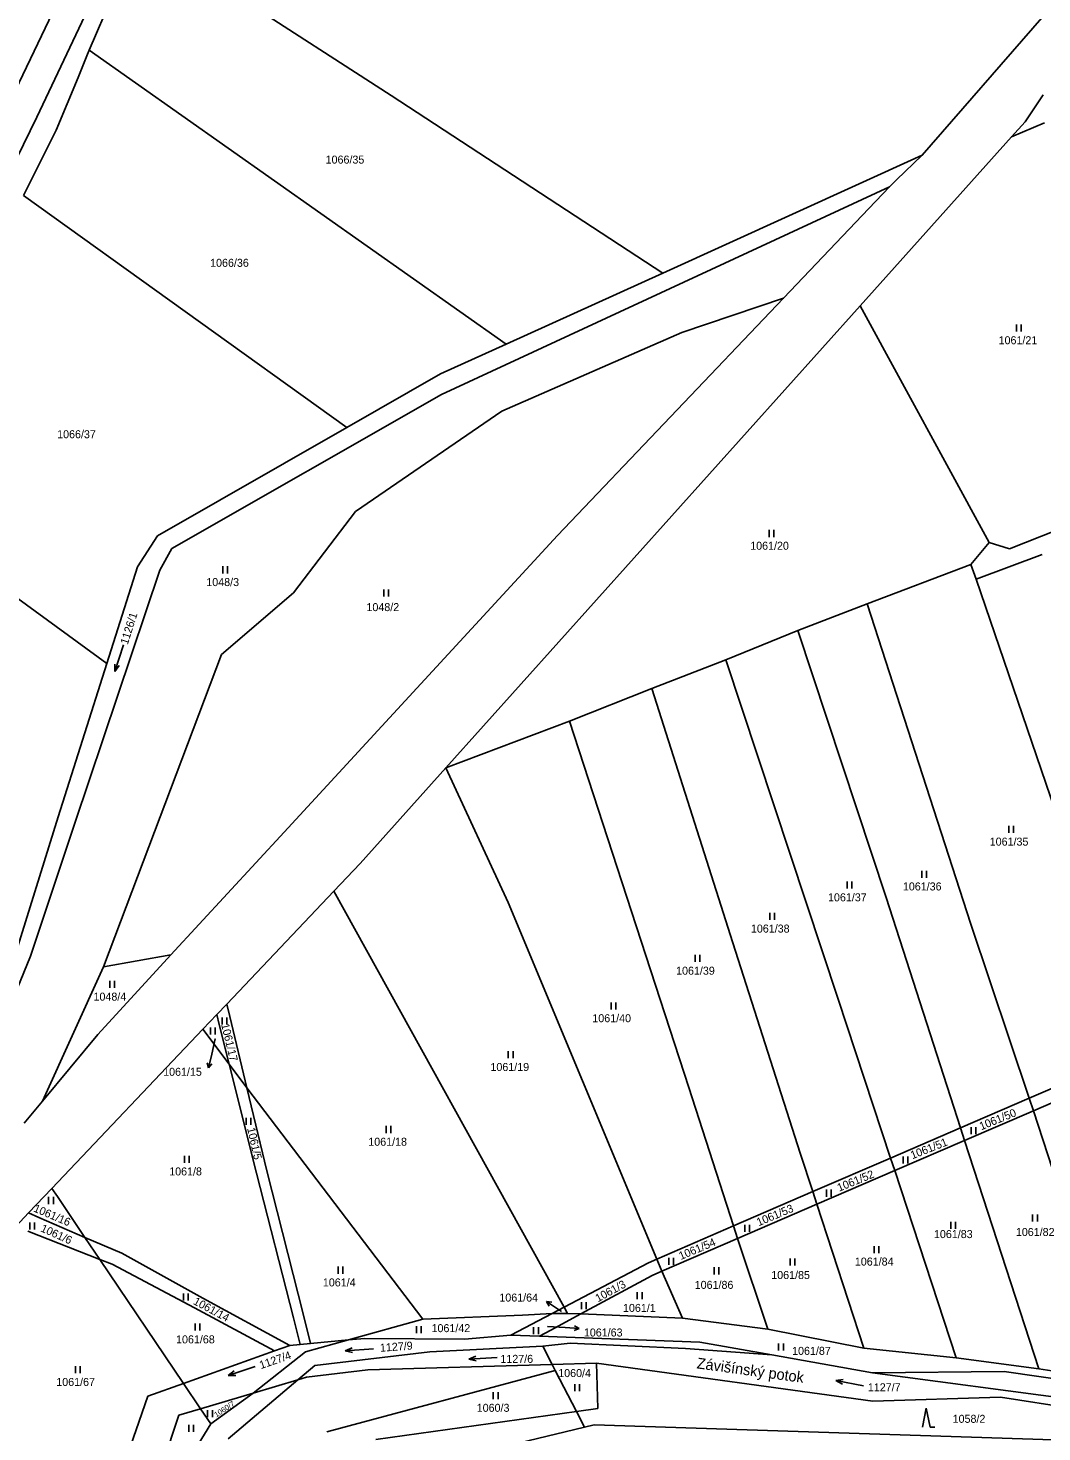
# Model space of a CAD drawing. Extents: x -794142 to -791199, y -1109267 to -1105626.
# Drawn here: x -791699.2 to -791483.8, y -1109116.1 to -1108817.8 of the extents above; entities that cross this region are included whole.
import ezdxf

# ---------------------------------------------------------------- set-up
doc = ezdxf.new("R2010")
doc.units = 0
for name, color, linetype in [('Komunikace', 7, 'Continuous'), ('Vrstva 1', 7, 'Continuous'), ('Vrstva 14', 7, 'Continuous'), ('Vrstva 16', 7, 'Continuous'), ('Vrstva 2', 7, 'Continuous'), ('Vrstva 23', 7, 'Continuous'), ('Vrstva 4', 7, 'Continuous'), ('Vrstva 44', 7, 'Continuous')]:
    doc.layers.add(name, color=color, linetype=linetype)

msp = doc.modelspace()

# ---------------------------------------------------------------- linework, layer by layer
at = {"layer": 'Komunikace'}
for p, q in [((-791659.43, -1109032.53), (-791660.18, -1109035.77)), ((-791585.87, -1109090.46), (-791586.52, -1109090.02)), ((-791588.86, -1109093.63), (-791585.1, -1109093.88))]:
    msp.add_line(p, q, dxfattribs=at)
at = {"layer": 'Vrstva 1'}
for p, q in [((-791675.71, -1108797.47), (-791622.06, -1108832.09)), ((-791686.2, -1108822.51), (-791677.63, -1108802.52)), ((-791509.23, -1108844.82), (-791483.82, -1108815.6)), ((-791686.55, -1108823.33), (-791688.52, -1108828.27)), ((-791686.55, -1108823.33), (-791686.2, -1108822.51)), ((-791597.62, -1108884.94), (-791686.2, -1108822.51)), ((-791688.52, -1108828.27), (-791693.25, -1108839.51)), ((-791622.06, -1108832.09), (-791564.37, -1108869.84)), ((-791487.36, -1108837.71), (-791483.53, -1108831.99)), ((-791693.25, -1108839.51), (-791700.19, -1108853.34)), ((-791490.23, -1108840.92), (-791487.36, -1108837.71)), ((-791490.23, -1108840.92), (-791483.28, -1108837.93)), ((-791522.4, -1108876.8), (-791490.23, -1108840.92)), ((-791509.23, -1108844.82), (-791564.37, -1108869.84)), ((-791514.67, -1108850.06), (-791509.23, -1108844.82)), ((-791611.34, -1108895.63), (-791516.16, -1108851.49)), ((-791520.56, -1108856.11), (-791516.16, -1108851.49)), ((-791516.16, -1108851.49), (-791514.67, -1108850.06)), ((-791700.19, -1108853.34), (-791631.47, -1108902.65)), ((-791538.73, -1108875.2), (-791520.56, -1108856.11)), ((-791597.62, -1108884.94), (-791564.37, -1108869.84)), ((-791586.7, -1108925.6), (-791538.73, -1108875.2)), ((-791538.73, -1108875.2), (-791560.31, -1108882.44)), ((-791610.45, -1108974.99), (-791522.4, -1108876.8)), ((-791495.01, -1108927.06), (-791522.4, -1108876.8)), ((-791560.31, -1108882.44), (-791598.56, -1108899.2)), ((-791611.6, -1108891.28), (-791597.62, -1108884.94)), ((-791631.47, -1108902.65), (-791611.6, -1108891.28)), ((-791611.34, -1108895.63), (-791668.66, -1108928.39)), ((-791598.56, -1108899.2), (-791629.66, -1108920.5)), ((-791671.68, -1108925.66), (-791631.47, -1108902.65)), ((-791490.67, -1108928.45), (-791453.12, -1108913.4)), ((-791731.94, -1108916.77), (-791682.45, -1108952.77)), ((-791629.66, -1108920.5), (-791642.8, -1108937.8)), ((-791675.94, -1108932.28), (-791671.68, -1108925.66)), ((-791644.8, -1108988.61), (-791586.7, -1108925.6)), ((-791668.66, -1108928.39), (-791671.18, -1108932.96)), ((-791498.91, -1108931.77), (-791495.01, -1108927.06)), ((-791495.01, -1108927.06), (-791490.67, -1108928.45)), ((-791520.9, -1108940.13), (-791498.91, -1108931.77)), ((-791498.91, -1108931.77), (-791497.78, -1108934.85)), ((-791497.78, -1108934.85), (-791483.78, -1108929.6)), ((-791689.18, -1108986.52), (-791671.18, -1108932.96)), ((-791682.45, -1108952.77), (-791675.94, -1108932.28)), ((-791497.78, -1108934.85), (-791470.8, -1109013.94)), ((-791642.8, -1108937.8), (-791658.1, -1108950.9)), ((-791535.68, -1108945.75), (-791520.9, -1108940.13)), ((-791498.91, -1109008.15), (-791520.9, -1108940.13)), ((-791550.94, -1108951.99), (-791535.68, -1108945.75)), ((-791535.68, -1108945.75), (-791516.92, -1109002.51)), ((-791692.81, -1108985.38), (-791682.45, -1108952.77)), ((-791658.1, -1108950.9), (-791683.18, -1109017.21)), ((-791566.7, -1108958.09), (-791550.94, -1108951.99)), ((-791550.94, -1108951.99), (-791527.06, -1109024.08)), ((-791584.16, -1108965.06), (-791566.7, -1108958.09)), ((-791566.7, -1108958.09), (-791549.44, -1109012.14)), ((-791610.45, -1108974.99), (-791584.16, -1108965.06)), ((-791584.16, -1108965.06), (-791558.83, -1109042.88)), ((-791610.45, -1108974.99), (-791628.62, -1108995.26)), ((-791610.45, -1108974.99), (-791597.22, -1109003.58)), ((-791692.81, -1108985.38), (-791701.75, -1109014.02)), ((-791698.7, -1109014.97), (-791689.18, -1108986.52)), ((-791668.84, -1109014.71), (-791644.8, -1108988.61)), ((-791628.62, -1108995.26), (-791634.22, -1109001.16)), ((-791634.22, -1109001.16), (-791656.97, -1109025.14)), ((-791634.22, -1109001.16), (-791585.29, -1109089.54)), ((-791565.62, -1109079.33), (-791597.22, -1109003.58)), ((-791516.92, -1109002.51), (-791501.13, -1109051.45)), ((-791486.5, -1109045.13), (-791498.91, -1109008.15)), ((-791535.13, -1109056.86), (-791549.44, -1109012.14)), ((-791713.72, -1109051.32), (-791698.7, -1109014.97)), ((-791684.39, -1109031.6), (-791668.84, -1109014.71)), ((-791683.18, -1109017.21), (-791668.84, -1109014.71)), ((-791683.18, -1109017.21), (-791696.11, -1109045.77)), ((-791527.06, -1109024.08), (-791515.95, -1109057.86)), ((-791662.06, -1109030.51), (-791659.11, -1109027.4)), ((-791659.11, -1109027.4), (-791656.97, -1109025.14)), ((-791659.11, -1109027.4), (-791658.58, -1109029.52)), ((-791656.34, -1109027.78), (-791656.97, -1109025.14)), ((-791656.48, -1109037.92), (-791658.58, -1109029.52)), ((-791652.69, -1109042.96), (-791656.34, -1109027.78)), ((-791696.11, -1109045.77), (-791684.39, -1109031.6)), ((-791694.15, -1109064.32), (-791662.06, -1109030.51)), ((-791662.06, -1109030.51), (-791656.48, -1109037.92)), ((-791463.58, -1109035.23), (-791486.5, -1109045.13)), ((-791656.48, -1109037.92), (-791652.69, -1109042.96)), ((-791650.69, -1109061.05), (-791656.48, -1109037.92)), ((-791462.67, -1109037.91), (-791485.62, -1109047.82)), ((-791652.69, -1109042.96), (-791615.31, -1109092.09)), ((-791648.44, -1109060.59), (-791652.69, -1109042.96)), ((-791549.34, -1109072.29), (-791558.83, -1109042.88)), ((-791501.13, -1109051.45), (-791486.5, -1109045.13)), ((-791485.62, -1109047.82), (-791486.5, -1109045.13)), ((-791700.01, -1109050.49), (-791696.11, -1109045.77)), ((-791485.62, -1109047.82), (-791500.26, -1109054.14)), ((-791478.5, -1109069.56), (-791485.62, -1109047.82)), ((-791515.95, -1109057.86), (-791501.13, -1109051.45)), ((-791500.26, -1109054.14), (-791515.07, -1109060.54)), ((-791501.13, -1109051.45), (-791500.26, -1109054.14)), ((-791500.26, -1109054.14), (-791484.45, -1109102.62)), ((-791535.13, -1109056.86), (-791532.47, -1109065)), ((-791532.47, -1109065), (-791515.95, -1109057.86)), ((-791515.95, -1109057.86), (-791515.07, -1109060.54)), ((-791650.69, -1109061.05), (-791642.82, -1109091.85)), ((-791648.44, -1109060.59), (-791640.69, -1109091.22)), ((-791515.07, -1109060.54), (-791531.6, -1109067.68)), ((-791515.07, -1109060.54), (-791501.99, -1109100.33)), ((-791699.1, -1109069.54), (-791694.15, -1109064.32)), ((-791694.15, -1109064.32), (-791692.97, -1109066.02)), ((-791687.1, -1109074.72), (-791692.97, -1109066.02)), ((-791549.34, -1109072.29), (-791532.47, -1109065)), ((-791532.47, -1109065), (-791531.6, -1109067.68)), ((-791531.6, -1109067.68), (-791548.47, -1109074.97)), ((-791531.6, -1109067.68), (-791521.62, -1109098.24)), ((-791701.79, -1109072.38), (-791699.1, -1109069.54)), ((-791699.1, -1109069.54), (-791696.87, -1109070.5)), ((-791696.87, -1109070.5), (-791687.1, -1109074.72)), ((-791699.27, -1109073.38), (-791683.92, -1109079.43)), ((-791683.92, -1109079.43), (-791687.1, -1109074.72)), ((-791687.1, -1109074.72), (-791679.28, -1109078.1)), ((-791565.62, -1109079.33), (-791549.34, -1109072.29)), ((-791548.47, -1109074.97), (-791564.54, -1109081.91)), ((-791548.47, -1109074.97), (-791549.34, -1109072.29)), ((-791542.04, -1109094.2), (-791548.47, -1109074.97)), ((-791679.28, -1109078.1), (-791662.05, -1109087.66)), ((-791666.16, -1109105.74), (-791683.92, -1109079.43)), ((-791683.92, -1109079.43), (-791681.35, -1109080.44)), ((-791663.82, -1109089.7), (-791681.35, -1109080.44)), ((-791585.29, -1109089.54), (-791567.4, -1109080.1)), ((-791565.62, -1109079.33), (-791567.4, -1109080.1)), ((-791564.54, -1109081.91), (-791565.62, -1109079.33)), ((-791581.75, -1109090.99), (-791566.6, -1109082.8)), ((-791566.6, -1109082.8), (-791564.54, -1109081.91)), ((-791560.18, -1109091.9), (-791564.54, -1109081.91)), ((-791646.81, -1109098.83), (-791663.82, -1109089.7)), ((-791643.6, -1109097.69), (-791662.05, -1109087.66)), ((-791587.88, -1109090.91), (-791585.29, -1109089.54)), ((-791584.56, -1109090.87), (-791585.29, -1109089.54)), ((-791641.38, -1109097.48), (-791642.82, -1109091.85)), ((-791640.69, -1109091.22), (-791639.16, -1109097.27)), ((-791631.14, -1109096.52), (-791615.31, -1109092.09)), ((-791615.31, -1109092.09), (-791594.15, -1109091.27)), ((-791596.61, -1109095.52), (-791587.88, -1109090.91)), ((-791594.15, -1109091.27), (-791587.88, -1109090.91)), ((-791588.11, -1109094.42), (-791581.75, -1109090.99)), ((-791587.88, -1109090.91), (-791584.56, -1109090.87)), ((-791581.75, -1109090.99), (-791584.56, -1109090.87)), ((-791581.75, -1109090.99), (-791560.18, -1109091.9)), ((-791560.18, -1109091.9), (-791542.04, -1109094.2)), ((-791606.47, -1109096.34), (-791596.61, -1109095.52)), ((-791590.56, -1109095.74), (-791596.61, -1109095.52)), ((-791588.11, -1109094.42), (-791590.56, -1109095.74)), ((-791590.56, -1109095.74), (-791556.45, -1109097.01)), ((-791542.04, -1109094.2), (-791521.62, -1109098.24)), ((-791666.16, -1109105.74), (-791646.81, -1109098.83)), ((-791651.35, -1109107.81), (-791640.22, -1109099.06)), ((-791643.6, -1109097.69), (-791646.81, -1109098.83)), ((-791641.38, -1109097.48), (-791643.6, -1109097.69)), ((-791639.16, -1109097.27), (-791641.38, -1109097.48)), ((-791640.22, -1109099.06), (-791631.14, -1109096.52)), ((-791639.16, -1109097.27), (-791631.14, -1109096.52)), ((-791638.28, -1109101.96), (-791613.81, -1109099.03)), ((-791631.14, -1109096.52), (-791627.61, -1109096.19)), ((-791627.61, -1109096.19), (-791606.47, -1109096.34)), ((-791613.81, -1109099.03), (-791589.82, -1109097.8)), ((-791589.82, -1109097.8), (-791584.04, -1109097.2)), ((-791587.85, -1109101.74), (-791589.82, -1109097.8)), ((-791584.04, -1109097.2), (-791559.55, -1109098.32)), ((-791559.55, -1109098.32), (-791541.19, -1109099.71)), ((-791541.19, -1109099.71), (-791556.45, -1109097.01)), ((-791521.62, -1109098.24), (-791501.99, -1109100.33)), ((-791641.85, -1109104.99), (-791638.28, -1109101.96)), ((-791627.01, -1109102.88), (-791587.85, -1109101.74)), ((-791587.85, -1109101.74), (-791578.4, -1109101.47)), ((-791587.21, -1109103.02), (-791587.85, -1109101.74)), ((-791578.4, -1109101.47), (-791519.69, -1109109.5)), ((-791578.4, -1109101.47), (-791578.16, -1109111.09)), ((-791519.76, -1109103.5), (-791541.19, -1109099.71)), ((-791501.99, -1109100.33), (-791484.45, -1109102.62)), ((-791656.65, -1109117.54), (-791641.85, -1109104.99)), ((-791651.35, -1109107.81), (-791641.85, -1109104.99)), ((-791641.85, -1109104.99), (-791640.03, -1109104.45)), ((-791640.03, -1109104.45), (-791627.01, -1109102.88)), ((-791587.21, -1109103.02), (-791635.72, -1109116.06)), ((-791582.71, -1109111.72), (-791587.21, -1109103.02)), ((-791491.85, -1109103.2), (-791519.76, -1109103.5)), ((-791519.76, -1109103.5), (-791465.44, -1109110.71)), ((-791467.16, -1109106.74), (-791491.85, -1109103.2)), ((-791484.45, -1109102.62), (-791466.81, -1109105.45)), ((-791673.74, -1109108.45), (-791666.16, -1109105.74)), ((-791662.52, -1109111.13), (-791666.16, -1109105.74)), ((-791662.52, -1109111.13), (-791651.35, -1109107.81)), ((-791660.34, -1109114.37), (-791651.35, -1109107.81)), ((-791681.73, -1109131.6), (-791673.74, -1109108.45)), ((-791492.63, -1109108.65), (-791519.69, -1109109.5)), ((-791466.86, -1109112.74), (-791492.63, -1109108.65)), ((-791675.53, -1109137.75), (-791667.17, -1109112.51)), ((-791667.17, -1109112.51), (-791662.52, -1109111.13)), ((-791660.34, -1109114.37), (-791662.52, -1109111.13)), ((-791625.28, -1109117.66), (-791582.71, -1109111.72)), ((-791582.71, -1109111.72), (-791578.16, -1109111.09)), ((-791580.99, -1109115.06), (-791582.71, -1109111.72)), ((-791660.34, -1109114.37), (-791679.78, -1109145.58))]:
    msp.add_line(p, q, dxfattribs=at)
at = {"layer": 'Vrstva 16'}
for p, q in [((-791660.18, -1109035.77), (-791660.858, -1109038.692)), ((-791660.858, -1109038.692), (-791661.119, -1109037.605)), ((-791660.858, -1109038.692), (-791660.145, -1109037.831)), ((-791586.52, -1109090.02), (-791589.016, -1109088.355)), ((-791589.016, -1109088.355), (-791588.461, -1109089.326)), ((-791589.016, -1109088.355), (-791587.906, -1109088.494)), ((-791585.1, -1109093.88), (-791582.106, -1109094.079)), ((-791582.106, -1109094.079), (-791583.137, -1109094.511)), ((-791582.106, -1109094.079), (-791583.071, -1109093.514))]:
    msp.add_line(p, q, dxfattribs=at)
at = {"layer": 'Vrstva 2'}
for p, q in [((-791697.29, -1108836.73), (-791680.77, -1108801.61)), ((-791689.47, -1108805.06), (-791706.93, -1108841.47)), ((-791725.89, -1108894.79), (-791697.29, -1108836.73))]:
    msp.add_line(p, q, dxfattribs=at)
at = {"layer": 'Vrstva 23'}
for p, q in [((-791489.22, -1108882.26), (-791489.22, -1108880.76)), ((-791488.22, -1108880.76), (-791488.22, -1108882.26)), ((-791541.76, -1108925.92), (-791541.76, -1108924.42)), ((-791540.76, -1108924.42), (-791540.76, -1108925.92)), ((-791657.83, -1108933.64), (-791657.83, -1108932.14)), ((-791656.83, -1108932.14), (-791656.83, -1108933.64)), ((-791623.63, -1108938.58), (-791623.63, -1108937.08)), ((-791622.63, -1108937.08), (-791622.63, -1108938.58)), ((-791678.92, -1108948.794), (-791680.759, -1108954.505)), ((-791680.759, -1108954.505), (-791680.775, -1108952.924)), ((-791680.759, -1108954.505), (-791679.823, -1108953.231)), ((-791490.83, -1108988.79), (-791490.83, -1108987.29)), ((-791489.83, -1108987.29), (-791489.83, -1108988.79)), ((-791509.29, -1108998.31), (-791509.29, -1108996.81)), ((-791508.29, -1108996.81), (-791508.29, -1108998.31)), ((-791525.16, -1109000.62), (-791525.16, -1108999.12)), ((-791524.16, -1108999.12), (-791524.16, -1109000.62)), ((-791541.6, -1109007.26), (-791541.6, -1109005.76)), ((-791540.6, -1109005.76), (-791540.6, -1109007.26)), ((-791557.47, -1109016.21), (-791557.47, -1109014.71)), ((-791556.47, -1109014.71), (-791556.47, -1109016.21)), ((-791681.82, -1109021.72), (-791681.82, -1109020.22)), ((-791680.82, -1109020.22), (-791680.82, -1109021.72)), ((-791575.3, -1109026.31), (-791575.3, -1109024.81)), ((-791574.3, -1109024.81), (-791574.3, -1109026.31)), ((-791660.46, -1109031.65), (-791660.46, -1109030.15)), ((-791659.46, -1109030.15), (-791659.46, -1109031.65)), ((-791657.98, -1109029.47), (-791657.98, -1109027.97)), ((-791656.98, -1109027.97), (-791656.98, -1109029.47)), ((-791597.16, -1109036.67), (-791597.16, -1109035.17)), ((-791596.16, -1109035.17), (-791596.16, -1109036.67)), ((-791652.88, -1109050.83), (-791652.88, -1109049.33)), ((-791651.88, -1109049.33), (-791651.88, -1109050.83)), ((-791623.13, -1109052.55), (-791623.13, -1109051.05)), ((-791622.13, -1109051.05), (-791622.13, -1109052.55)), ((-791498.84, -1109052.81), (-791498.84, -1109051.31)), ((-791497.84, -1109051.31), (-791497.84, -1109052.81)), ((-791665.94, -1109058.86), (-791665.94, -1109057.36)), ((-791664.94, -1109057.36), (-791664.94, -1109058.86)), ((-791513.3, -1109059.03), (-791513.3, -1109057.53)), ((-791512.3, -1109057.53), (-791512.3, -1109059.03)), ((-791694.82, -1109067.64), (-791694.82, -1109066.14)), ((-791693.82, -1109066.14), (-791693.82, -1109067.64)), ((-791529.57, -1109066.08), (-791529.57, -1109064.58)), ((-791528.57, -1109064.58), (-791528.57, -1109066.08)), ((-791698.8, -1109073.04), (-791698.8, -1109071.54)), ((-791697.8, -1109071.54), (-791697.8, -1109073.04)), ((-791546.9, -1109073.53), (-791546.9, -1109072.03)), ((-791545.9, -1109072.03), (-791545.9, -1109073.53)), ((-791503.15, -1109072.89), (-791503.15, -1109071.39)), ((-791502.15, -1109071.39), (-791502.15, -1109072.89)), ((-791485.77, -1109071.35), (-791485.77, -1109069.85)), ((-791484.77, -1109069.85), (-791484.77, -1109071.35)), ((-791519.43, -1109078.07), (-791519.43, -1109076.57)), ((-791518.43, -1109076.57), (-791518.43, -1109078.07)), ((-791633.3, -1109082.44), (-791633.3, -1109080.94)), ((-791632.3, -1109080.94), (-791632.3, -1109082.44)), ((-791563.07, -1109080.55), (-791563.07, -1109079.05)), ((-791562.07, -1109079.05), (-791562.07, -1109080.55)), ((-791553.43, -1109082.58), (-791553.43, -1109081.08)), ((-791552.43, -1109081.08), (-791552.43, -1109082.58)), ((-791537.26, -1109080.71), (-791537.26, -1109079.21)), ((-791536.26, -1109079.21), (-791536.26, -1109080.71)), ((-791666.2, -1109088.16), (-791666.2, -1109086.66)), ((-791665.2, -1109086.66), (-791665.2, -1109088.16)), ((-791569.76, -1109087.86), (-791569.76, -1109086.36)), ((-791568.76, -1109086.36), (-791568.76, -1109087.86)), ((-791581.61, -1109089.96), (-791581.61, -1109088.46)), ((-791580.61, -1109088.46), (-791580.61, -1109089.96)), ((-791663.72, -1109094.54), (-791663.72, -1109093.04)), ((-791662.72, -1109093.04), (-791662.72, -1109094.54)), ((-791616.69, -1109095.09), (-791616.69, -1109093.59)), ((-791615.69, -1109093.59), (-791615.69, -1109095.09)), ((-791591.78, -1109095.28), (-791591.78, -1109093.78)), ((-791590.78, -1109093.78), (-791590.78, -1109095.28)), ((-791631.823, -1109098.813), (-791630.36, -1109098.212)), ((-791625.836, -1109098.406), (-791631.823, -1109098.813)), ((-791631.823, -1109098.813), (-791630.292, -1109099.21)), ((-791539.73, -1109098.78), (-791539.73, -1109097.28)), ((-791538.73, -1109097.28), (-791538.73, -1109098.78)), ((-791605.545, -1109100.571), (-791604.076, -1109099.986)), ((-791599.554, -1109100.228), (-791605.545, -1109100.571)), ((-791605.545, -1109100.571), (-791604.019, -1109100.984)), ((-791689.11, -1109103.59), (-791689.11, -1109102.09)), ((-791688.11, -1109102.09), (-791688.11, -1109103.59)), ((-791650.967, -1109102.12), (-791656.652, -1109104.04)), ((-791656.652, -1109104.04), (-791655.391, -1109103.086)), ((-791656.652, -1109104.04), (-791655.071, -1109104.033)), ((-791527.576, -1109105.137), (-791526.009, -1109104.927)), ((-791600.35, -1109109.08), (-791600.35, -1109107.58)), ((-791599.35, -1109107.58), (-791599.35, -1109109.08)), ((-791583.06, -1109107.4), (-791583.06, -1109105.9)), ((-791582.06, -1109105.9), (-791582.06, -1109107.4)), ((-791521.683, -1109106.262), (-791527.576, -1109105.137)), ((-791527.576, -1109105.137), (-791526.197, -1109105.909)), ((-791509.17, -1109115.02), (-791508.37, -1109111.02)), ((-791508.37, -1109111.02), (-791507.57, -1109115.02)), ((-791661.04, -1109112.94), (-791661.04, -1109111.44)), ((-791660.04, -1109111.44), (-791660.04, -1109112.94)), ((-791665.06, -1109116.05), (-791665.06, -1109114.55)), ((-791664.06, -1109114.55), (-791664.06, -1109116.05)), ((-791507.57, -1109115.02), (-791506.57, -1109115.02))]:
    msp.add_line(p, q, dxfattribs=at)
at = {"layer": 'Vrstva 4'}
for p, q in [((-791630.72, -1109126.97), (-791580.99, -1109115.06)), ((-791580.99, -1109115.06), (-791578.9, -1109114.56)), ((-791578.9, -1109114.56), (-791466.68, -1109118.19))]:
    msp.add_line(p, q, dxfattribs=at)

# ---------------------------------------------------------------- texts
at = {"layer": 'Vrstva 14'}
for s, height, p in [('1066/35', 1.7, (-791635.969, -1108846.58)), ('1066/36', 1.7, (-791660.512, -1108868.51)), ('1061/21', 1.7, (-791492.998, -1108884.96)), ('1066/37', 1.7, (-791693.009, -1108904.93)), ('1061/20', 1.7, (-791545.774, -1108928.62)), ('1048/3', 1.7, (-791661.318, -1108936.34)), ('1048/2', 1.7, (-791627.298, -1108941.66)), ('1061/35', 1.7, (-791494.892, -1108991.49)), ('1061/36', 1.7, (-791513.336, -1109001.01)), ('1061/37', 1.7, (-791529.242, -1109003.32)), ('1061/38', 1.7, (-791545.625, -1109009.96)), ('1061/39', 1.7, (-791561.516, -1109018.91)), ('1048/4', 1.7, (-791685.284, -1109024.42)), ('1061/40', 1.7, (-791579.31, -1109029.01)), ('1061/15', 0.1, (-791659.683, -1109032.53)), ('1061/19', 1.7, (-791600.959, -1109039.37)), ('1061/18', 1.7, (-791626.908, -1109055.25)), ('1061/8', 1.7, (-791669.205, -1109061.56)), ('1061/83', 1.7, (-791506.735, -1109074.87)), ('1061/82', 1.7, (-791489.335, -1109074.43)), ('1061/84', 1.7, (-791523.541, -1109080.71)), ('1061/4', 1.7, (-791636.561, -1109085.14)), ('1061/86', 1.7, (-791557.565, -1109085.66)), ('1061/85', 1.7, (-791541.302, -1109083.57)), ('1061/1', 1.7, (-791572.799, -1109090.56)), ('1061/42', 1.7, (-791613.471, -1109094.86)), ('1061/64', 0.1, (-791586.135, -1109090.46)), ('1061/68', 1.7, (-791667.745, -1109097.24)), ('1061/63', 0.1, (-791589.127, -1109093.63)), ('1061/87', 1.7, (-791536.872, -1109099.68)), ('1127/6', 1.7, (-791598.843, -1109101.38)), ('1061/67', 1.7, (-791693.192, -1109106.29)), ('1060/4', 1.7, (-791586.557, -1109104.4)), ('1127/7', 1.7, (-791520.779, -1109107.42)), ('1060/3', 1.7, (-791603.872, -1109111.78)), ('1058/2', 1.7, (-791502.768, -1109114.12))]:
    msp.add_text(s, height=height, dxfattribs=at).set_placement(p)
for s, height, rotation, p in [('1126/1', 1.7, 72.41445, (-791678.026, -1108948.894)), ('1061/17', 1.7, 283.72437, (-791658.188, -1109029.488)), ('1061/50', 1.7, 22.22442, (-791496.683, -1109051.981)), ('1061/5', 1.7, 282.67389, (-791652.664, -1109051.56)), ('1061/51', 1.7, 21.56445, (-791511.323, -1109058.136)), ('1061/52', 1.7, 22.23909, (-791526.884, -1109065.029)), ('1061/16', 1.7, 336.94758, (-791698.175, -1109069.176)), ('1061/53', 1.7, 22.79808, (-791543.985, -1109072.367)), ('1061/6', 1.7, 335.82087, (-791696.663, -1109073.389)), ('1061/54', 1.7, 22.82553, (-791560.512, -1109079.54)), ('1061/3', 1.7, 28.56015, (-791578.115, -1109088.53)), ('1061/14', 1.7, 331.71786, (-791664.244, -1109088.824)), ('1127/4', 1.7, 19.08351, (-791649.71, -1109102.718)), ('1127/9', 1.7, 4.10544, (-791624.363, -1109099.033)), ('1060/7', 1.14, 33.65334, (-791659.185, -1109113.018))]:
    msp.add_text(s, height=height, rotation=rotation, dxfattribs=at).set_placement(p)
at = {"layer": 'Vrstva 16'}
for s, p in [('1061/15', (-791670.49, -1109040.39)), ('1061/64', (-791599.063, -1109088.36)), ('1061/63', (-791581.11, -1109095.78))]:
    msp.add_text(s, height=1.7, dxfattribs=at).set_placement(p)
at = {"layer": 'Vrstva 44'}
msp.add_text('Závišínský potok', height=2.3, rotation=352.21635, dxfattribs=at).set_placement((-791557.23, -1109102.54))

doc.saveas('drawing.dxf')
